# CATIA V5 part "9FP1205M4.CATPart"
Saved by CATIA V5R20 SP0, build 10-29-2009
Part number: 9FP1205M4
Revision: ANY
Definition: UNKNOWN
Nomenclature: 9FP1205M4
Source: Unknown
Bounding box of the stored display mesh (mm): x -5.752 to 5.752, y 0 to 5, z -5.9 to 5.9
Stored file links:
  C:\Users\Utente\Desktop\IO LAVORO\3D X SITO CF\CUMSA\3D files PW\pw060630\pw060630_ejection\9FP1205M4.CATPart
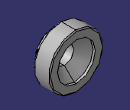
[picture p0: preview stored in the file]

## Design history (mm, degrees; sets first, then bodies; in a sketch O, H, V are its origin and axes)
Body1 "Redondeo2" (main body)
  Solid1: solid without history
